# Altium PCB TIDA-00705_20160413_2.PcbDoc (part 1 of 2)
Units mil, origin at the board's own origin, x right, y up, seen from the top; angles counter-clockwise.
Board outline 1000 x 1000 mil, 6 copper layers (Top Layer, L2-GND-PLANE, L3-BUS, L4-BAT, L5-GND 1-PLANE, Bottom Layer), stack 0 mil thick; 66 components, 35 nets, 184 pads, 221 vias.
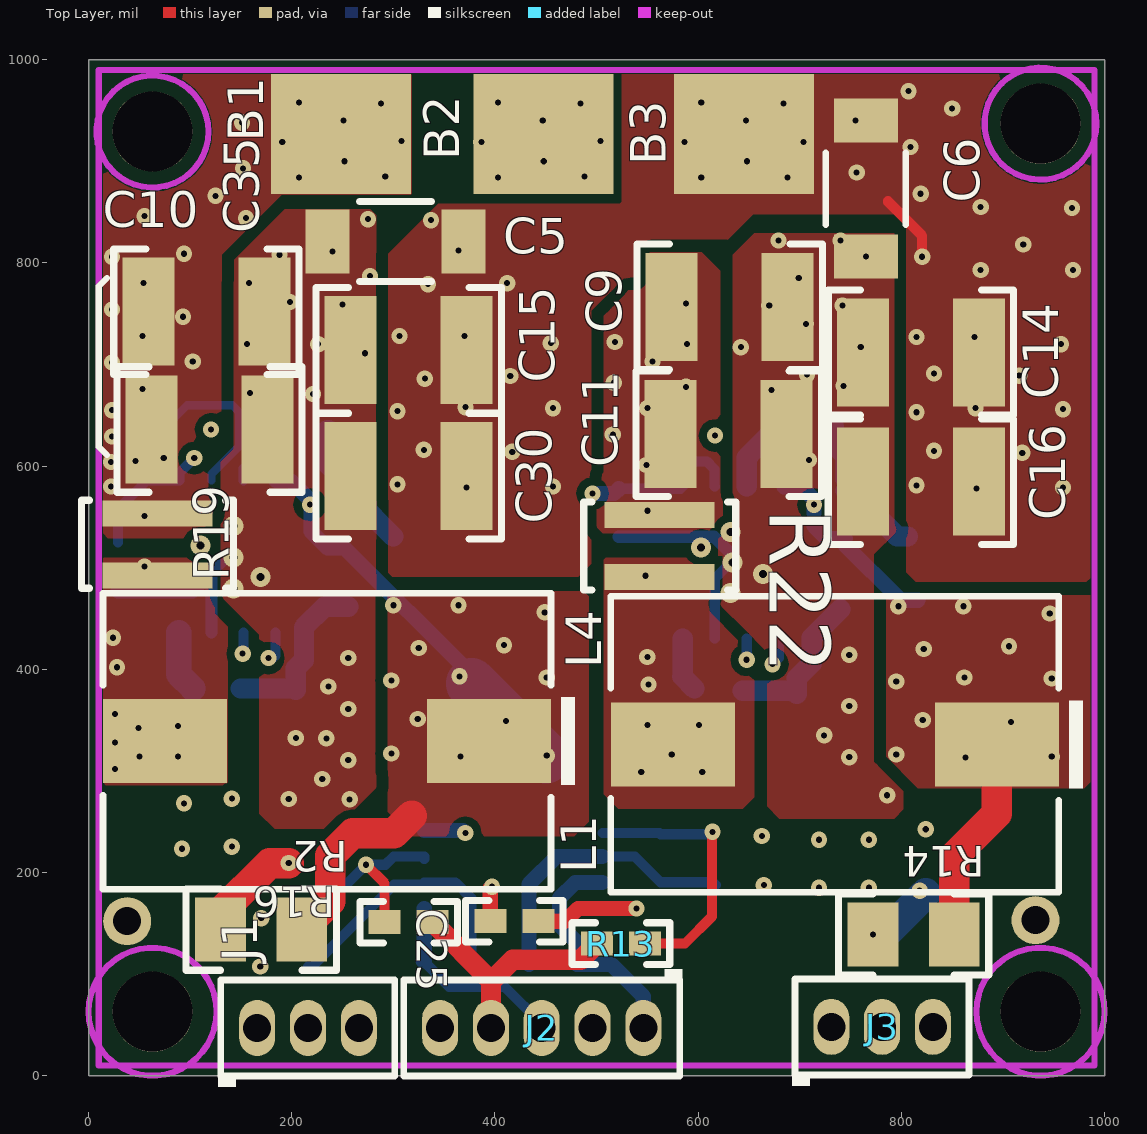
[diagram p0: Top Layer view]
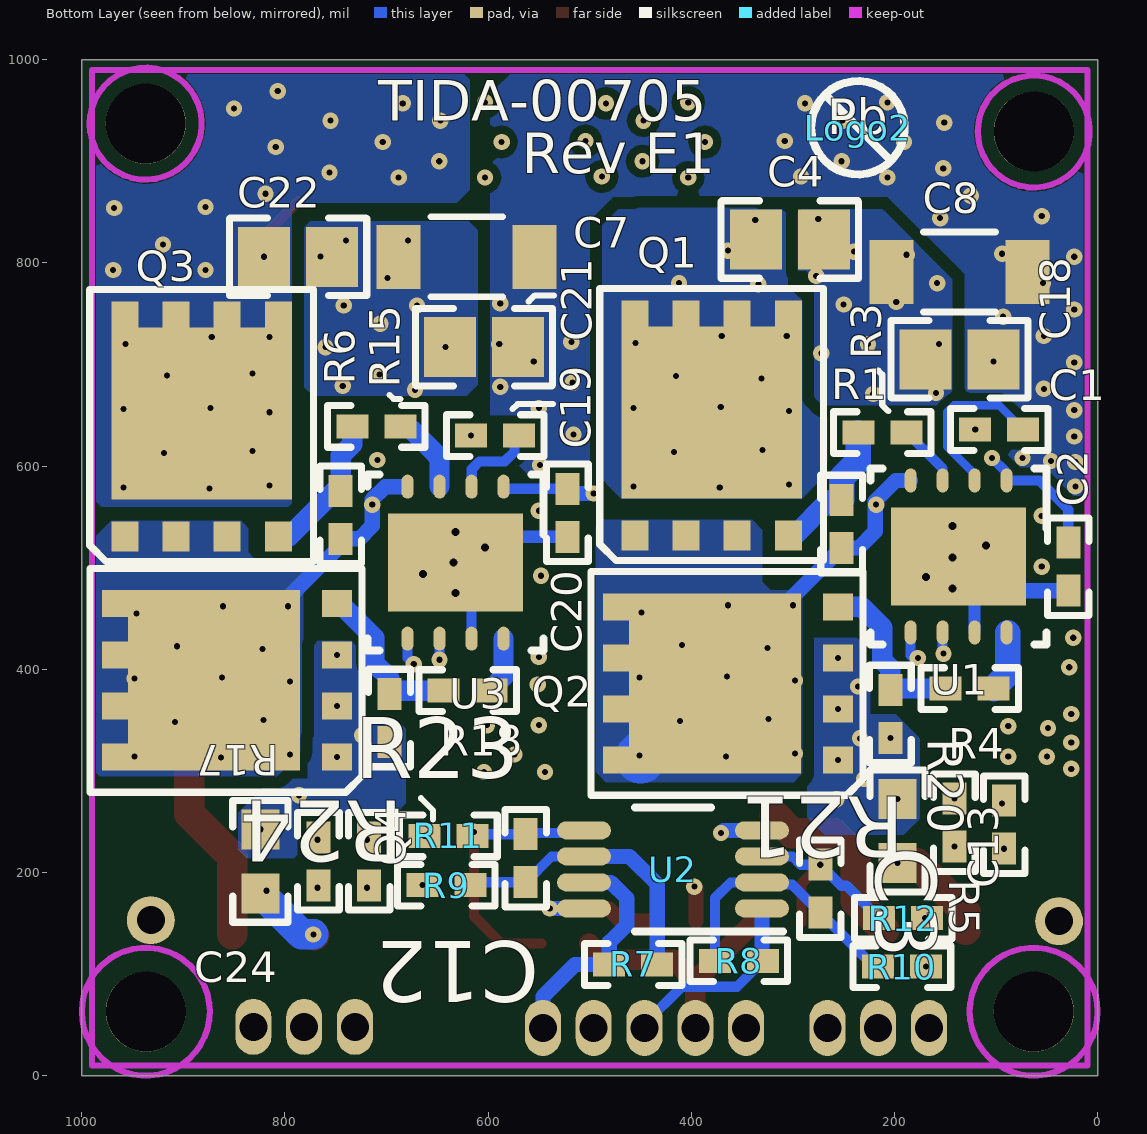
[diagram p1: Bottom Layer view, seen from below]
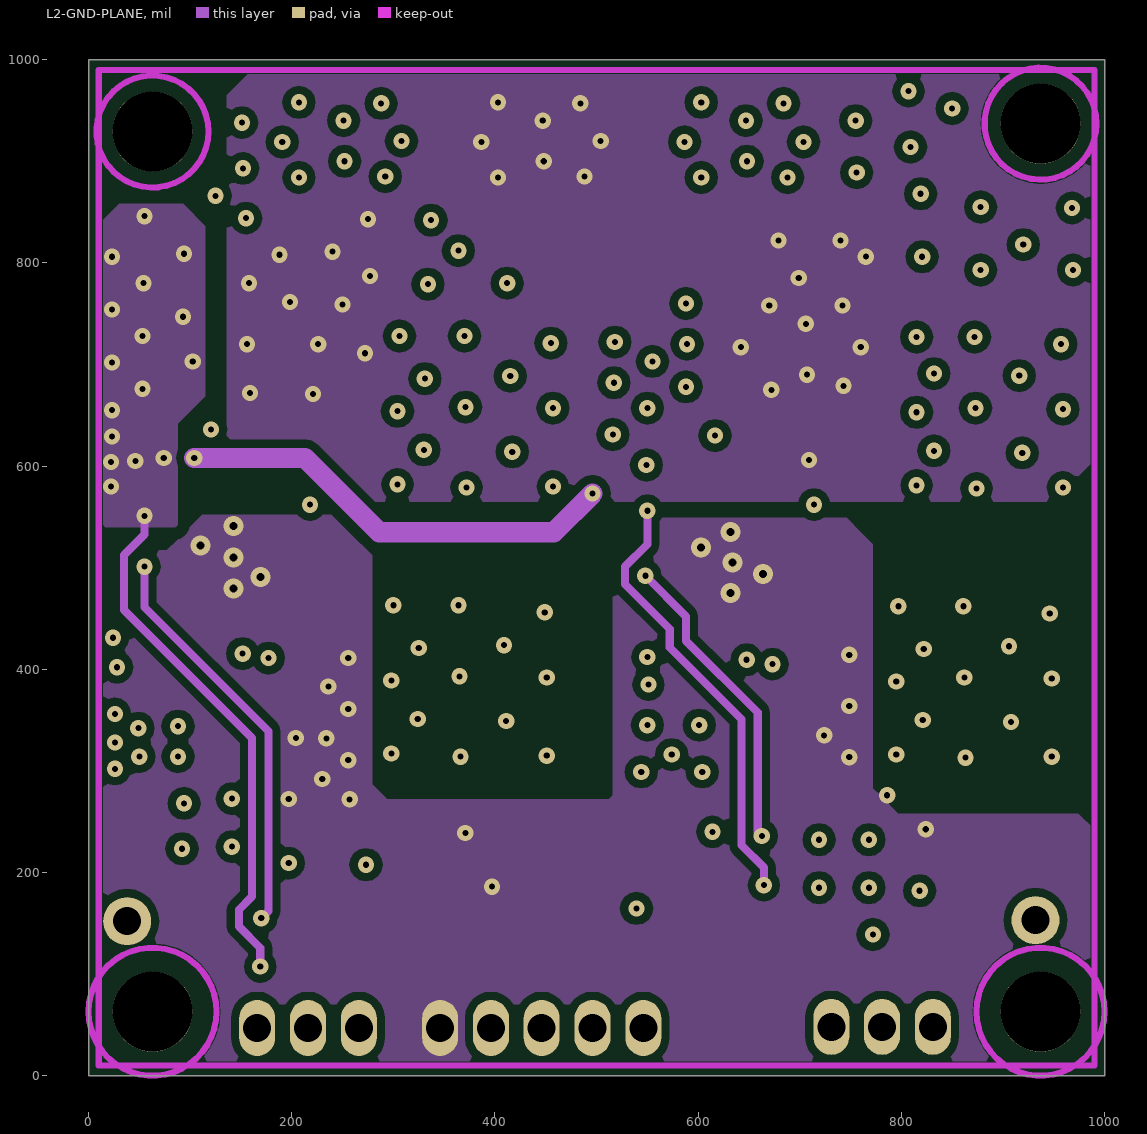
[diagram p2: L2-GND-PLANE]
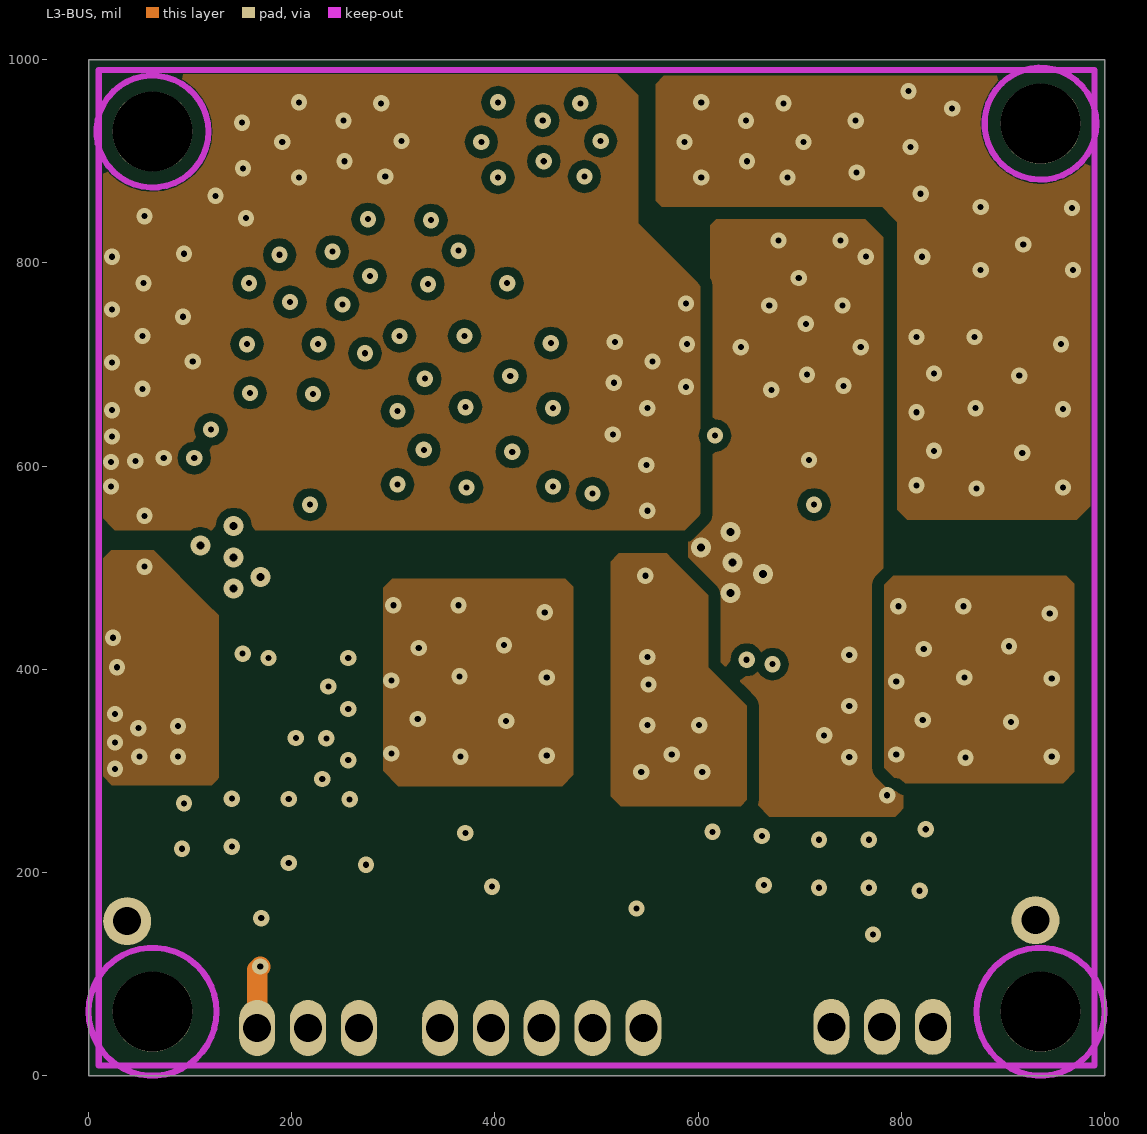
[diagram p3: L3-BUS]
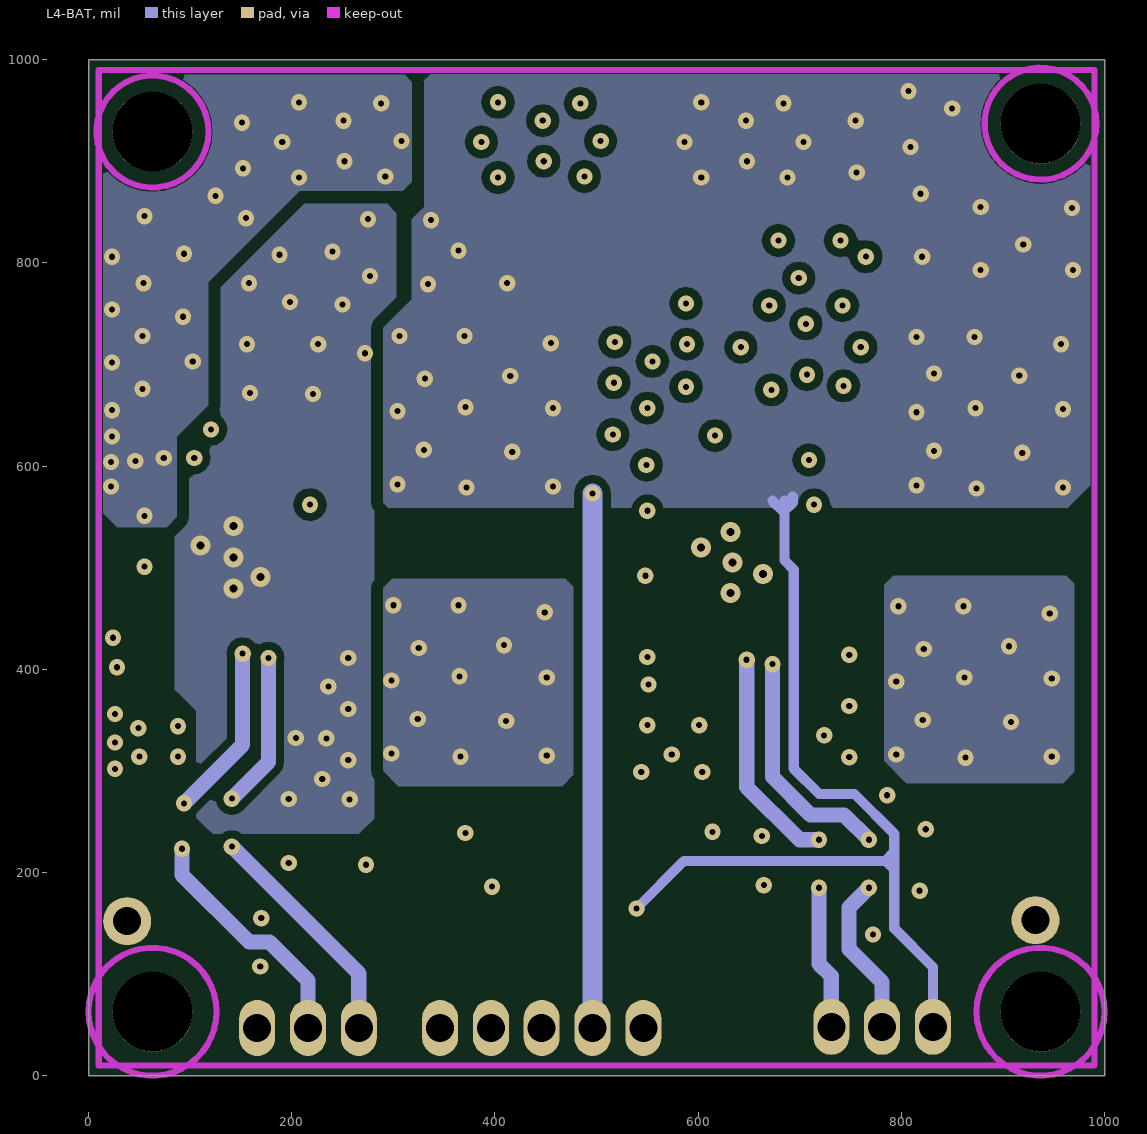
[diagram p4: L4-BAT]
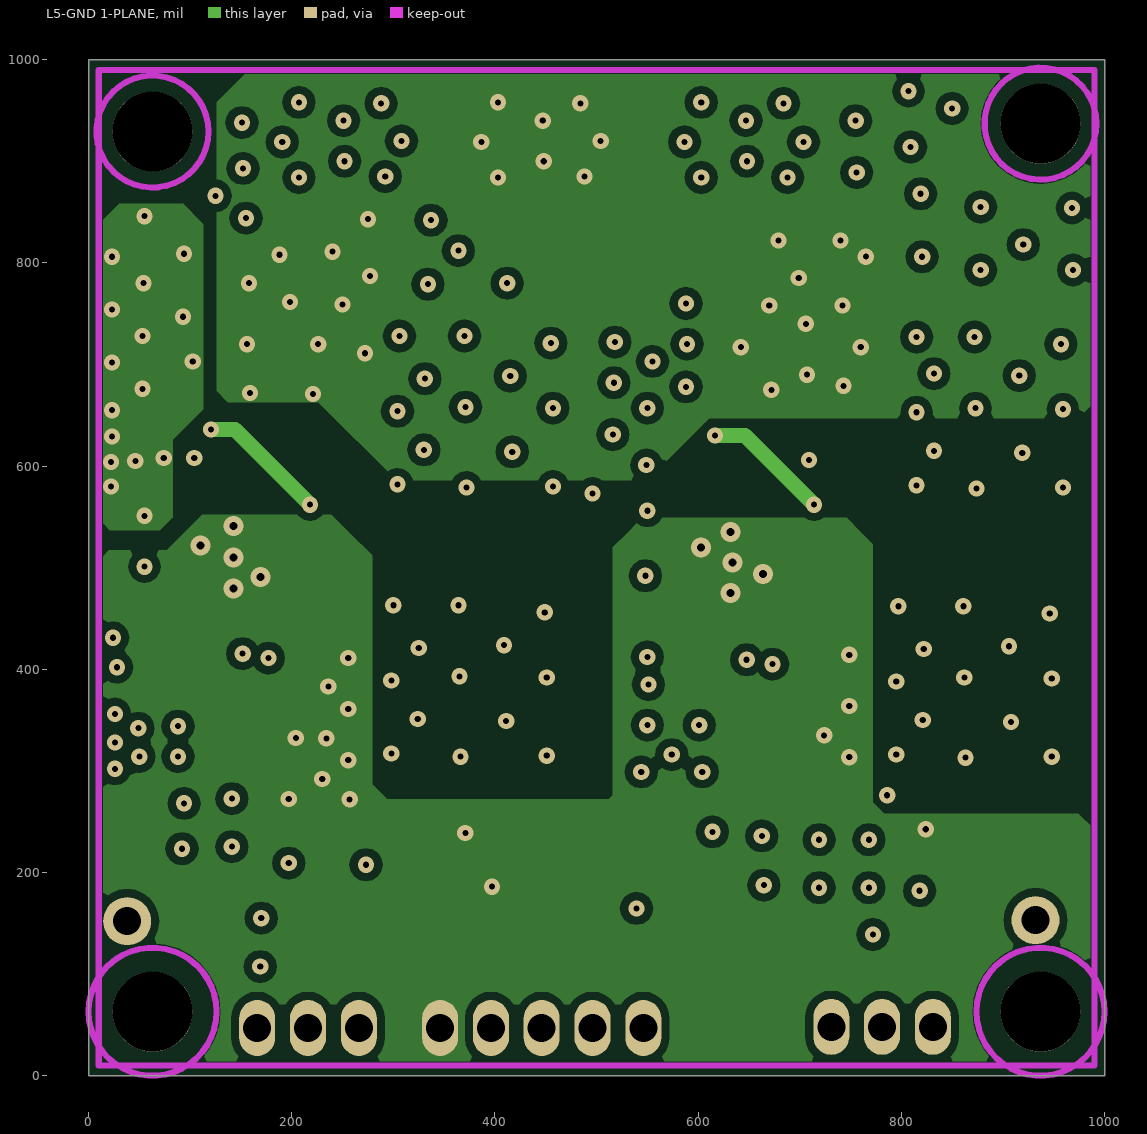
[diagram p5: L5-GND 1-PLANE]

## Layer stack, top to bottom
Top Layer: signal copper (thickness not stored)
L2-GND-PLANE: signal copper (thickness not stored)
L3-BUS: signal copper (thickness not stored)
L4-BAT: signal copper (thickness not stored)
L5-GND 1-PLANE: signal copper (thickness not stored)
Bottom Layer: signal copper (thickness not stored)

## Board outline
0,0 1000,0 1000,1000 0,1000

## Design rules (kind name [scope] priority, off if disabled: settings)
AcuteAngle [All] p1: minimum=4.50000000000000E+0001 checktracksonly=FALSE
AssemblyTestPointUsage [All] p1: valid=2
Clearance Keepout_via [IsKeepOut vs IsVia] p1: gap=1 except(6: Via-Via SMDPad-Via THPad-Via Track-Via)
Clearance Keepout_Polygon [IsKeepOut vs InPolygon] p2: gap=1
Clearance U2 [InComponent('U2') vs InComponent('U2')] p3: gap=7.5
Clearance "Clearance_Via to SMD" [IsVia vs IsSMTPin] p4: gap=0 except(6: SMDPad-Via Track-Via THPad-Via; 8: Via-Via)
Clearance keepout [IsKeepOut vs (InPadClass('All Pads'))] p5: gap=0.5
Clearance "Clearance_Poly to Poly" [InPolygon vs InPolygon] p6: gap=12
Clearance "Clearance_VIA TO VIA" [IsVia vs IsVia] p7: gap=8
Clearance Clearance_BoardEdge_MountingHoles [OnCopper and InComponentClass('Mounting Holes') vs IsKeepOut] p8: gap=40
Clearance [All] p9: gap=8
ComponentClearance ComponentClearance_1 [All] p1: gap=0 collisioncheckmode=3 verticalgap=0 showdistances=FALSE
DiffPairsRouting [All] p1: maxlimit=100 minlimit=10 mostfreqgap=10 toplayer_minwidth=15 toplayer_maxwidth=15 toplayer_prefwidth=15 midlayer1_minwidth=15 midlayer1_maxwidth=15 midlayer1_prefwidth=15 midlayer2_minwidth=15 midlayer2_maxwidth=15 midlayer2_prefwidth=15 midlayer3_minwidth=15 midlayer3_maxwidth=15 midlayer3_prefwidth=15 midlayer4_minwidth=15 midlayer4_maxwidth=15 midlayer4_prefwidth=15 bottomlayer_minwidth=15 bottomlayer_maxwidth=15 bottomlayer_prefwidth=15 maxuncoupledlength=1000
FabricationTestPointUsage TestPointUsage [All] p1: valid=2 allowmultiple=FALSE
FabricationTestpoint Testpoint [All] p1: side=3 testpointundercomponent=TRUE minsize=40 maxsize=100 preferedsize=60 minholesize=0 maxholesize=40 preferedholesize=32 testpointgrid=1 allowsidetop=TRUE allowsidebottom=TRUE usegrid=TRUE gridtolerance=0.01
FanoutControl Fanout_LCC [IsLCC] p1: bgadir=Out bgaviamode=Centered fanoutstyle=Auto fanoutdirection=Alternating viagrid=1 // Fanout_LCC (Default Rule)
FanoutControl Fanout_BGA [IsBGA] p2: bgadir=Out bgaviamode=Centered fanoutstyle=Auto fanoutdirection=Alternating viagrid=1 // Fanout_BGA (Default Rule)
FanoutControl Fanout_Default [All] p4: bgadir=Out bgaviamode=Centered fanoutstyle=Auto fanoutdirection=Alternating viagrid=1 // Fanout_Default (Default Rule)
FanoutControl Fanout_Small [(CompPinCount < 5)] p5: bgadir=Out bgaviamode=Centered fanoutstyle=Auto fanoutdirection=OutThenIn viagrid=1 // Fanout_Small (Default Rule)
HoleSize [All] p1: absolutevalues=TRUE maxlimit=251 minlimit=6 maxpercent=80.000 minpercent=20.000
MatchedLengths DiffPair_MatchedLengths_1 [All] p1: tolerance=1000 checknetsindiffpair=TRUE checkdiffpairvsdiffpair=TRUE checkothers=TRUE
MatchedLengths DiffPair_MatchedLengths_2 [InDifferentialPair ('NewDifferentialPair2')] p2: tolerance=1000 checknetsindiffpair=TRUE checkdiffpairvsdiffpair=TRUE checkothers=TRUE
MatchedLengths il1MatchedLengths [InDifferentialPair ('NewDifferentialPair1')] p3: tolerance=1000 checknetsindiffpair=TRUE checkdiffpairvsdiffpair=TRUE checkothers=TRUE
MatchedLengths DiffPair_MatchedLengths_3 [InDifferentialPair ('NewDifferentialPair1')] p4: tolerance=1000 checknetsindiffpair=TRUE checkdiffpairvsdiffpair=TRUE checkothers=TRUE
MatchedLengths DiffPair_MatchedLengths_4 [InDifferentialPair ('OP AMP')] p5: tolerance=1000 checknetsindiffpair=TRUE checkdiffpairvsdiffpair=TRUE checkothers=TRUE
MatchedLengths DiffPair_MatchedLengths_1_1 [InDifferentialPair ('OP AMP')] p6: tolerance=1000 checknetsindiffpair=TRUE checkdiffpairvsdiffpair=TRUE checkothers=TRUE
MinimumAnnularRing MinimumAnnularRing_1 [(InComponent('J1') AND InComponent('J2') AND InComponent('J3'))] p1: minimumring=3
MinimumAnnularRing MinimumAnnularRing_ThermalPadVias [IsVia and InAnyComponent] p2: minimumring=3
MinimumAnnularRing [All] p3: minimumring=3
MinimumSolderMaskSliver MinimumSolderMaskSliver_Logo [InComponentClass('Logo') vs InComponentClass('Logo')] p1: minsoldermaskwidth=0.7
MinimumSolderMaskSliver [All] p2: minsoldermaskwidth=3.94
PlaneClearance [All] p1: clearance=16
PlaneConnect [All] p1: planeconnectstyle=Direct reliefexpansion=10 reliefentries=4 reliefconductorwidth=10 reliefairgap=10
PolygonConnect [All] p1: connectstyle=Direct reliefconductorwidth=10 reliefentries=4 polygonreliefangle="90 Angle" airgapwidth=10
RoutingVias ThermalPadVias [IsVia and InAnyComponent] p1: holewidth=7.87 width=19.68 viastyle="Through Hole" minholewidth=7.87 minwidth=19.68 maxholewidth=12.99 maxwidth=23.62
RoutingVias RoutingVias_PWR [All] p2: holewidth=6 width=16 viastyle="Through Hole" minholewidth=6 minwidth=16 maxholewidth=7.78 maxwidth=19.68
RoutingVias [All] p3: holewidth=6 width=16 viastyle="Through Hole" minholewidth=6 minwidth=16 maxholewidth=6 maxwidth=16
SMDToCorner [All] p1: distance=30000
SilkToBoardRegionClearance [All] p1 off:
SilkToSilkClearance [All] p1 off: silktosilkclearance=5
SilkToSolderMaskClearance SilkscreenOverComponentPads [IsPad] p1 off: minsilkscreentomaskgap=5 clearancetoexposedcopper=TRUE
SolderMaskExpansion [All] p1: expansion=2.5
UnpouredPolygon [All] p1: allowunpoured=FALSE
ViasUnderSMD [All] p1: allowed=TRUE
Width Width_PWR [InNetClass('PWR')] p1: maxlimit=100 minlimit=8 preferedwidth=8
Width [All] p2: maxlimit=100 minlimit=6 preferedwidth=8 checkconnectedcopper=TRUE
13 further rules are at their usual default settings.

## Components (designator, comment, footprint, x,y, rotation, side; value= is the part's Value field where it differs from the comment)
B1 "SMD" B1#1 1507.87,123 r180 top
B2 "SMD" B1#2 1314.87,123 r180 top
B3 "SMD" B1#3 1121.87,123 r180 top
C1 "06033C104JAT2A" 0402 96.87,636 r0 bottom
C2 "GRM188R61E105KA12D" 0402 28.87,501 r270 bottom
C3 "885012205031" 0402 273,184 r90 bottom
C4 "12103C106KAT2A" 0805 303,823 r180 bottom
C5 "12103C106KAT2A" 1206_190 302,821 r180 top
C6 "12103C106KAT2A" 1206_190 765,873 r270 top
C7 "12103C106KAT2A" 1206_190 621,806 r0 bottom
C8 "12103C106KAT2A" 1206_190 136,791 r0 bottom
C9 "12103C106KAT2A" 1210 631,756.72 r0 top
C10 "12103C106KAT2A" 1210 119,636 r0 top
C11 "12103C106KAT2A" 1210 630,631.72 r0 top
C12 "885012205031" 0402 563,214 r90 bottom
C13 "06031C222KAT2A" 0603 197,240.69 r90 bottom
C14 "12103C106KAT2A" 1210 819.24,711.69 r180 top
C15 "12103C106KAT2A" 1210 315.04,714 r180 top
C16 "12103C106KAT2A" 1210 819.24,584.69 r180 top
C18 "12103C106KAT2A" 0805 136,705 r0 bottom (schematic designator C8)
C19 "06033C104JAT2A" 0402 593,630 r0 bottom
C20 "GRM188R61E105KA12D" 0402 521.87,554 r270 bottom
C21 "12103C106KAT2A" 0805 604,717 r0 bottom
C22 "12103C106KAT2A" 0805 787,806 r180 bottom
C24 "06031C222KAT2A" 0603 824,211 r90 bottom
C25 "C0603C104Z4VACTU" 0402 419,152 r180 top
C30 "12103C106KAT2A" 1210 315.04,590 r180 top
C35 "12103C106KAT2A" 1210 116,752 r0 top
J1 "GRPB031VWVN-RC" Sullins_GRPB031VWVN-RC 216,47 r0 top locked
J2 "GRPB051VWVN-RC" Sullins_GRPB051VWVN-RC 446,47 r180 top locked
J3 "GRPB031VWVN-RC" Sullins_GRPB031VWVN-RC 781,48 r0 top locked
L1 "FP1107R1-R23-R" FP1107R1 234.6,329.15 r180 top
L4 "FP1107R1-R23-R" FP1107R1 734.47,326.15 r180 top
Logo1 "Texas Instruments" TI_Symbol_Overlay_Small 587,-159 r180 bottom
Logo2 "Pb-Free Symbol" Pb-Free_Overlay_Small 236,933 r180 bottom
Q1 "CSD16325Q5C" TRANS_NexFET_Q5C 380,641 r90 bottom locked
Q2 "CSD16325Q5C" TRANS_NexFET_Q5C 364.87,386 r0 bottom locked
Q3 "CSD16325Q5C" TRANS_NexFET_Q5C 882,640 r90 bottom
Q4 "CSD16325Q5C" TRANS_NexFET_Q5C 858,389 r0 bottom
R1 "CRCW04021K05FKED" 0402 252,543 r90 bottom
R2 "RR1220Q-100-D" 0805_HV 169.88,143.72 r0 top
R3 "CRCW04020000Z0ED" 0402 212,633 r0 bottom
R4 "CRCW04020000Z0ED" 0402 126,381 r0 bottom
R5 "CRCW04021K05FKED" 0402 141,249 r270 bottom
R6 "CRCW04021K05FKED" 0402 745,552 r90 bottom
R7 "CRCW04021K05FKED" 0402 457.13,109.42 r0 bottom
R8 "CRCW04021K05FKED" 0402 353.13,113 r180 bottom
R9 "CRCW04021K05FKED" 0402 641,187.5 r180 bottom
R10 "CRCW04021K05FKED" 0402 192.62,107.35 r0 bottom
R11 "CRCW04021K05FKED" 0402 639,236 r180 bottom
R12 "CRCW04021K05FKED" 0402 191.5,155 r0 bottom
R13 "CRCW04021K05FKED" 0402 524,130 r0 top
R14 "RR1220Q-100-D" 0805_HV 812,139 r0 top
R15 "CRCW04020000Z0ED" 0402 710,639 r0 bottom
R16 "CRCW04021K05FKED" 0402 315,151 r180 top
R17 "CRCW04021K05FKED" 0402 767,211 r270 bottom
R18 "CRCW04020000Z0ED" 0402 620,379 r0 bottom
R19 "PRL1632-R005-F-T1" 0612 68,523 r90 top
R20 "CRCW04021K05FKED" 0402 92,247 r270 bottom
R21 "CRCW04021K05FKED" 0402 204,356 r90 bottom
R22 "PRL1632-R005-F-T1" 0612 562.13,521.28 r90 top
R23 "CRCW04021K05FKED" 0402 717,211 r270 bottom
R24 "CRCW04021K05FKED" 0402 697,352 r90 bottom
U1 "UCC27211D" DRM0008A 136.87,511 r270 bottom
U2 "OPA2192IDGKR" DGK0008A_N 418,203 r0 bottom
U3 "UCC27211D" DRM0008A 632,505 r270 bottom

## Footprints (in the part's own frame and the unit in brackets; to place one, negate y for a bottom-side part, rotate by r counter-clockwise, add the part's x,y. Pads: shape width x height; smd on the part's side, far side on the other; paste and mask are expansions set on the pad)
0402 [mm] "0402 from SM-752 data"
  rect 0.8x0.6 smd: 1(-0.6,0) 2(0.6,0)
  silkscreen extent -1.22,-0.52 1.22,0.52, body extent -0.55,-0.3 0.55,0.3, height 0.6
0603 [mm] "0603 from SM-752 data"
  rect 1x0.95 smd: 1(-0.8,0) 2(0.8,0)
  silkscreen extent -1.52,-0.69 1.52,0.69, body extent -0.87,-0.47 0.87,0.47, height 1
0612 [mm] "Panasonic recommended land pattern, fb97d03ed01.pdf dated April 2008"
  rect 0.65x2.75 smd: 1(-0.775,0) 2(0.775,0)
  silkscreen extent -1.1,-1.9 1.1,1.9, body extent -0.9,-1.7 0.9,1.7, height 0.85
0805 [mm] "0805 from SM-752 data"
  rect 1.3x1.5 smd: 1(-0.85,0) 2(0.85,0)
  silkscreen extent -1.72,-0.97 1.72,0.97, body extent -1.1,-0.72 1.1,0.72, height 1.45
0805_HV [mil] "0805 with 30mil clearance between pads"
  rect 50x63 smd: 1(-40,0) 2(40,0)
  silkscreen extent -74,-40 74,40, body extent -43,-29 43,29, height 57
1206_190 [mm] "1206_190"
  rect 1.1x1.6 smd: 1(-1.7,0) 2(1.7,0)
  silkscreen extent -0.9,-1 0.9,1, body extent -1.75,-0.95 1.75,0.95, height 1.9
1210 [mm] "1210 from SM-752 data"
  rect 1.3x2.7 smd: 1(-1.45,0) 2(1.45,0)
  silkscreen extent -2.32,-1.57 2.32,1.57, body extent -1.7,-1.35 1.7,1.35, height 1.35
B1#1 [mm]
  rect 3.5x3 smd: 1(31.991,-20.422)
B1#2 [mm]
  rect 3.5x3 smd: 1(22.027,-20.422)
B1#3 [mm]
  rect 3.5x3 smd: 1(12.113,-20.422)
DGK0008A_N [mm] "TSOP, 8-Leads, Body 3x3mm, Pitch 0.65mm, IPC Medium Density"
  oval 1.35x0.45 smd: 1(-2.225,0.975) 2(-2.225,0.325) 3(-2.225,-0.325) 4(-2.225,-0.975) 5(2.225,-0.975) 6(2.225,-0.325) 7(2.225,0.325) 8(2.225,0.975)
  silkscreen extent -2.75,-1.55 0.95,1.55, body extent -2.45,-1.5 2.45,1.5, height 0.96
DRM0008A [mm] "TI"
  oval 0.6x0.3 smd: 1(-1.9,1.2) 2(-1.9,0.4) 3(-1.9,-0.4) 4(-1.9,-1.2) 5(1.9,-1.2) 6(1.9,-0.4) 7(1.9,0.4) 8(1.9,1.2)
  rect 2.45x3.38 smd paste-1.25: 9(0,0)
  silkscreen extent -2.2,-2.2 2.2,2.2, body extent -2.05,-2.05 2.05,2.05, height 1.01
FP1107R1 [mm] "COILTRONICS"
  rect 3.1x2.1 smd: 1(-4.05,0) 2(4.05,0)
  silkscreen extent -6.2,-3.7 5.6,3.7, body extent -5.5,-3.6 5.5,3.6, height 7.51
Pb-Free_Overlay_Small [mil]
  silkscreen extent -46,-46 46,46
Sullins_GRPB031VWVN-RC [mm] "SULLINS"
  oval 0.9x1.4 hole 0.7: 1(-1.27,0) 2(0,0) 3(1.27,0)
  silkscreen extent -2.25,-1.47 2.17,1.2, body extent -2.15,-1.17 2.17,1.17, height 4.2
Sullins_GRPB051VWVN-RC [mm] "SULLINS"
  oval 0.9x1.4 hole 0.7: 1(-2.54,0) 2(-1.27,0) 3(0,0) 4(1.27,0) 5(2.54,0)
  silkscreen extent -3.52,-1.47 3.45,1.2, body extent -3.42,-1.17 3.42,1.17, height 4.2
TI_Symbol_Overlay_Small [mil]
  silkscreen extent -90,-88 91,88
TRANS_NexFET_Q5C [mm] "TI recommended land pattern (nominal) M0139-01"
  rect 0.75x0.675 smd mask+0.051: 1(-2.776,1.917) 2(-2.776,0.639) 3(-2.776,-0.639) 4(-2.776,-1.917)
  rect 0.655x0.675 smd mask+0.051: 5(2.776,-1.917) 6(2.776,-0.639) 7(2.776,0.639) 8(2.776,1.917)
  rect 4.295x4.51 smd paste-2.2 mask+0.051: 10(0.301,0)
  silkscreen extent -3.4,-2.8 3.4,2.8, body extent -3.05,-2.55 3.05,2.55, height 1.06

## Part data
B1 B2 B3: library part TP_30X40MIL, "Test Point, SM, 2x3mm"
C1 C19: "CAP, CERM, 0.1 µF, 25 V, +/- 5%, X7R, 0603"
C2 C20: "CAP, CERM, 1 µF, 25 V, +/- 10%, X5R, 0603"
C3 C12: "CAP, CERM, 0.01 µF, 16 V, +/- 10%, X7R, 0402"
C4 C5 C6 C7 C8 C9 C10 C11 C14 C15 C16 C18 C21 C22 C30 C35: "CAP, CERM, 10 µF, 25 V, +/- 10%, X7R, 1210"
C13 C24: "CAP, CERM, 2200 pF, 100 V, +/- 10%, X7R, 0603"
C25: "CAP, CERM, 0.1 µF, 16 V, +80/-20%, Y5V, 0603"
J1 J3: "Header, 50mil, 3x1, Gold, TH"
J2: "Header, 50mil, 5x1, Gold, TH"
L1 L4: "Inductor, Wirewound, Ferrite, 230nH, 45A, 0.00029 ohm, SMD"
Logo1: library part TI_Logo, "Texas Instrument Corporate Signature"
Logo2: library part Pb-Free
Q1 Q2 Q3 Q4: "MOSFET, N-CH, 25 V, 100 A, DualCool SON 5x6mm"
R1 R5 R6 R7 R8 R9 R10 R11 R12 R13 R16 R17 R20 R21 R23 R24: "RES, 1.05 k, 1%, 0.063 W, 0402"
R2 R14: "RES, 10.0, 0.5%, 0.1 W, 0805"
R3 R4 R15 R18: "RES, 0, 5%, 0.063 W, 0402"
R19 R22: "RES, 0.0005, 1%, 1 W, 0612"
U1 U3: "120-V Boot, 4-A Peak, High Frequency High-Side and Low-Side Driver, D0008A"
U2: "36-V, Precision, Rail-to-Rail Input/Output, Low Offset Voltage, Low Input Bias Current Op Amp with e-trim, DGK0008A"

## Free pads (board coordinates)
  round 47.24 hole 27.56: 0(38,152) 0(932,153)
  round 78.74 hole 78.74 unplated mask+10: 0(62.87,929.25) 0(62.99,62.99) 0(936.87,62.99) 0(937.01,937.01)

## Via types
v1: diameter 16, hole 6, Top Layer to Bottom Layer, 211 vias
v2: diameter 19.68, hole 7.87, Top Layer to Bottom Layer, 10 vias

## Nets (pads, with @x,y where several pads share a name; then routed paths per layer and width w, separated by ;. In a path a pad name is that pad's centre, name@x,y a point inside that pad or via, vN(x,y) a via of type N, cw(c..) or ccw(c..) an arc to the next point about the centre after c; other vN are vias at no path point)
8.2V: C2.1 C20.1 J2.2 U1.1 U3.1 | length 1188.9
  L2-GND-PLANE w20: v1(104,608) 213,608 286,535 458,535 v1(496,573)
  L4-BAT w20: J2.2@496,47 v1(496,573)
  Bottom Layer w10: C2.1@28.87,524.62 28.87,557.18 57.5,585.8 U1.1@89.63,585.8 89.63,593.63 v1(104,608) ; C20.1@521.87,577.62 582.57,577.62 U3.1@584.76,579.8
  Bottom Layer w15: v1(496,573) 517.25,573 C20.1@521.87,577.62
BAT+: B3.1 C4.1 C5.1 C6.1 C14.1 C15.1 C16.1 C22.1 C25.1 C30.1 J3.3 Q1.5 Q1.6 Q1.7 Q1.8 Q1.10 Q3.5 Q3.6 Q3.7 Q3.8 Q3.10 U2.8 | length 1125.8
  Top Layer w10: 787,861 787,860 820.46,826.54 v1(820.46,806)
  Top Layer w15: C25.1@442.62,152 469,152 481.61,164.61 v1(539.28,164.61)
  L4-BAT w10: v1(539.28,164.61) 585.91,211.24 784,211.24 ; 673,566 684,555 ; 685,566 685,556 ; 693.04,570 693.04,564.04 685,556 ; J3.3@831,59 831,107 793,145 793,203 ; 684,555 685,555 ; 684,555 685,556 ; 685,555 685,556 ; 685,555 685,507.15 694.13,498.02 694.13,302.18 719.15,277.15 753.85,277.15 793,238 793,220.24 ; 784,211.24 784.76,211.24 ; 784,211.24 793,220.24 ; 784.76,211.24 793,211.24 ; 784.76,211.24 793,203 ; 793,203 793,211.24 ; 793,211.24 793,220.24
  L4-BAT w15: v1(539.28,164.61) v1@539.9,164
  Bottom Layer w15: U2.8@505.6,164.61 v1(539.28,164.61)
  other v1: 874,578 372,579 959,579 457,580 815,581 304,582 919,613 417,614 832,615 330,616 815,653 304,654 959,656 457,657 873,657 371,658 331,686 415,688.69 916,689 832,691 957,720 455,721 815,727 872,727 306,728 370,728 334,779 412,780 878,793 969,793 364,812 920,818 337,842 968,854 878,855 819,868 603,884 688,884 756,889 648,900 809,914 586.61,919 703.61,919 647,940 755,939.93 850,952 684,957 603,958 807,969
BUS+: B1.1 C7.1 C8.1 C9.1 C10.1 C11.1 C18.1 C21.1 C35.1 J1.1 R9.1 R10.1 R19.2 R22.2 | length 1022.6
  Top Layer w20: J1.1@165,41 J1.1@171,35
  L2-GND-PLANE w8: v1(55,551) 55,532.63 35,512.63 35,458.37 161,332.37 161,176.41 147.88,163.28 147.88,146.72 169,125.59 v1(169,107.35) ; v1(550,556) 550,523 528,501 528,483.72 572,439.72 572,421.37 642.62,350.75 642.62,226.8 664.62,204.8 v1(664.62,187.5)
  L3-BUS w20: J1.1@166,47 166,104.35 v1(169,107.35)
  other v1: 22,580 549,601 22,604 46,605 74,608 23,629 516,631 23,655 550,657 53,676 588,678 517,682 23,702 102.54,703 555,703 589,720 518,722 53,728 93,747 23,754 588,760 54,780 23,806 94,809 155,844 55,846 125,866 207,884 292,885 152,893 252,900 190.61,919 308,920 151,938 251,940 288,957 207,958
GND: B2.1 C2.2 C4.2 C5.2 C6.2 C7.2 C8.2 C9.2 C10.2 C11.2 C13.2 C14.2 C15.2 C16.2 C18.2 C20.2 C21.2 C22.2 C24.2 C25.2 C30.2 C35.2 J2.5 Q2.1 Q2.2 Q2.3 Q4.1 Q4.2 Q4.3 R21.1 R24.1 U1.7 U1.9 U2.4 U3.7 U3.9 | length 456.8
  Top Layer w15: C25.2@395.38,152 395.38,184.38 v1(397,186)
  Bottom Layer w10: U3.7@616.25,430.2 616.25,489.25 U3.9@632,505 v2(634,505)
  Bottom Layer w12: U1.7@121.13,436.2 121.13,494.25 120.13,495.25 U1.9@135.87,511 ; C20.2@521.87,530.38 615.62,530.38 U3.9@632,514
  Bottom Layer w15: C2.2@28.87,477.38 102.25,477.38 U1.9@120.13,495.25 ; U2.4@330.4,241.39 368.22,241.39 v1(370.8,238.8)
  other v1: 824,242.5 197,272.19 257,272 786,276 230,292 255.57,310.51 748.7,313.51 204,332.38 234,332 724,335 255.57,360.84 748.7,363.84 236,383 255.57,411.16 748.7,414.16 709,606 221,671 159,672 672,675 743,679 707,690 272,711 642,717 760,717 156,720 226,720 706,740 670,758 742,758 250,759 198.25,761.46 158,780 699,785 277,787 765,806.07 188,808 240,811 679,822 740,822 275,843 403,884 488,885 448,900 386.61,919 504,920 447,940 484,957 403,958
  other v2: 632,475 142.8,479.69 169,491 664,494 142.8,510 603,520 110,522 632,535 142.8,541
H1_PWM: J1.3 R5.2 | length 230.2
  L4-BAT w15: v1(141,225.38) 266,100.38 J1.3@266,47
H2_PWM: J3.2 R17.2 | length 158.5
  L4-BAT w15: v1(768,185) 748.5,165.5 748.5,124.5 781,92 J3.2@781,48
IL1: J2.3 R8.2 U2.1 | length 198.1
  Bottom Layer w10: R8.2@329.51,113 354.95,87.56 409.43,87.56 446,50.99 J2.3@446,47
  Bottom Layer w15: R8.2@329.51,113 330.4,113.89 U2.1@330.4,164.61
IL1+: L1.2 R12.1 R19.1 | length 399.4
  L2-GND-PLANE w8: v1(55,501) 55,461 177,339 177,162 v1(170,155)
  other v1: 26,302 50,314 88,314 26,328 49,342 88,344 26,356 28,402 24,431
IL2: J2.1 R7.2 U2.7 | length 230.2
  Bottom Layer w15: U2.7@505.6,190.2 479.03,190.2 463.52,174.7 463.52,148.48 480.76,131.24 R7.2@480.76,109.42 514.58,109.42 546,78 J2.1@546,47
IL2+: L4.2 R11.1 R22.1 | length 303.5
  L2-GND-PLANE w8: v1(548,492) 588,452 588,428 658.62,357.38 658.62,240 v1(662.62,236)
  other v1: 544,299 604,299 574,316 550,345 601,345 551,385 550,412
L1_PWM: J1.2 R20.2 | length 248.6
  L5-GND 1-PLANE w15: J1.2@219,48 J1.2@225.5,54.5
  L4-BAT w15: v1(92,223.38) 92,197.64 158.14,131.5 178.08,131.5 216,93.58 J1.2@216,47
L2_PWM: J3.1 R23.2 | length 142
  L4-BAT w15: v1(719,185) 719,110 731,98 J3.1@731,48
NetC1_1: C1.1 U1.2 | length 166.2
  Bottom Layer w8: C1.1@73.25,636 97.06,659.81 141.56,659.81 148.24,653.13 148.24,619.22 121.13,592.1 U1.2@121.13,585.8
NetC1_2: C1.2 L1.1 Q1.1 Q1.2 Q1.3 Q2.5 Q2.6 Q2.7 Q2.8 Q2.10 R1.1 R2.2 U1.4 | length 710.5
  Top Layer w30: R2.2@209.88,143.72 237.88,171.72 237.88,216.34 260.16,238.62 300.62,238.62 318,256
  L5-GND 1-PLANE w15: v1(120.5,636) 144,636 v1(218,562)
  Bottom Layer w15: U1.4@184.12,585.8 198.76,585.8 218.91,565.65 218.91,562.09 219,562 219,535.5 235.12,519.38 R1.1@252,519.38 376.74,394.64 Q2.10@376.74,386
  Bottom Layer w50: Q2.10@376.74,386 Q2.10@449.96,312.78
  other v1: 366,314 451,315 298,317 411,349 324,351 298,389 451,392 365,393 325,421 409,423.69 449,456 300,463 364,463
NetC3_1: C3.1 R8.1 R10.2 U2.2 | length 266.6
  Bottom Layer w10: R10.2@216.24,107.35 219.97,107.35 C3.1@273,160.38 300.65,188.03 328.23,188.03 U2.2@330.4,190.2 361.3,190.2 376.76,174.74 R8.1@376.76,113 R8.1@376.76,109.42
NetC3_2: C3.2 R12.2 R16.2 U2.3 | length 204.8
  Top Layer w10: v1(273,207.62) 291.38,189.24 R16.2@291.38,151
  Bottom Layer w10: R12.2@215.12,155 247.12,187 252.38,187 v1(273,207.62) 292.12,207.62 300.3,215.8 U2.3@330.4,215.8 ; U2.3@330.4,213.21 U2.3@330.54,213.21
NetC12_1: C12.1 R7.1 R9.2 U2.6 | length 286
  Bottom Layer w10: U2.6@505.6,215.8 537.58,215.8 C12.1@563,190.38 614.5,190.38 R9.2@617.38,187.5
  Bottom Layer w15: R7.1@433.51,109.42 433.51,188.51 460.8,215.8 U2.6@505.6,215.8
NetC12_2: C12.2 R11.2 R13.2 U2.5 | length 269.1
  Top Layer w10: R13.2@547.62,130 587,130 613.76,156.76 613.76,239.76 v1(614,240)
  Bottom Layer w10: U2.5@505.73,238.8 561.82,238.8 C12.2@563,237.62 R11.2@613.76,237.62
NetC13_1: C13.1 R2.1 | length 104.3
  Top Layer w30: R2.1@129.88,143.72 129.88,160.84 178.23,209.2 v1(197,209.2)
NetC19_1: C19.1 U3.2 | length 83.1
  Bottom Layer w10: C19.1@569.38,629 574,624.38 574,614.19 583.57,604.61 608.39,604.61 616,597 616,580.06 U3.2@616.25,579.8
NetC19_2: C19.2 L4.1 Q3.1 Q3.2 Q3.3 Q4.5 Q4.6 Q4.7 Q4.8 Q4.10 R6.1 R14.2 U3.4 | length 522.2
  Top Layer w30: R14.2@852,139 852,216 893.92,257.92 L4.1@893.92,326.15
  L5-GND 1-PLANE w15: v1(616.62,630) 646.04,630 v1(714.04,562)
  Bottom Layer w15: U3.4@684.45,579.55 701.44,579.55 714.04,566.96 v1(714.04,562) 714.04,541 726.66,528.38 R6.1@745,528.38 ; R6.1@744,523 799,468 Q4.10@816.38,468
  other v1: 863,313 948,314 795,316 908,348 821,350 795,388 948,391 862,392 822,420 906,422.69 946,455 797,462 861,462
NetC24_1: C24.1 R14.1 | length 70.2
  Top Layer w30: R14.1@771,138 v1(772,139)
  Bottom Layer w30: v1(772,139) 783.5,139 822.25,177.75 C24.1@824,179.5
  other v1: 818,182
NetQ1_4: Q1.4 R1.2 R3.2 | length 135.9
  Bottom Layer w20: R1.2@252,566.62 263.77,566.62 Q1.4@299.8,530.6
  Bottom Layer w25: R3.2@235.62,633 235.62,604.87 252,588.5 R1.2@252,566.62
NetQ2_4: Q2.4 R4.2 R21.2 | length 171.8
  Bottom Layer w20: R4.2@149.62,381 202.62,381 R21.2@204,379.62 204,401 212,409 212,441.13 232.37,461.49 Q2.4@255.57,461.49
NetQ3_4: Q3.4 R6.2 R15.2 | length 137.2
  Bottom Layer w20: R15.2@733.62,639 733.62,621.38 745,610 R6.2@745,586.62 ; R6.2@745,575.62 750.77,575.62 795.7,530.7 Q3.4@806.51,530.7
NetQ4_4: Q4.4 R18.2 R24.2 | length 155.9
  Bottom Layer w20: R18.2@643.62,379 693.62,379 R24.2@697,375.62 697,391 711.81,405.81 711.81,430.94 Q4.4@739.87,459
NetR3_1: R3.1 U1.3 | length 56.9
  Bottom Layer w10: U1.3@152.62,585.8 152.62,597.62 178.38,623.38 R3.1@178.38,632
NetR4_1: R4.1 U1.8 | length 60.9
  Bottom Layer w25: U1.8@88.63,436.2 88.63,395.12 102.38,381.37 R4.1@102.38,381
NetR5_1: R5.1 U1.5 | length 180.3
  L4-BAT w15: v1(141,272.62) 177,308.62 v1(177,411)
  Bottom Layer w10: v1@181,410.53 184.12,413.64 U1.5@184.12,436.2
NetR15_1: R15.1 U3.3 | length 67.6
  Bottom Layer w20: U3.3@647.75,579.8 647.75,608.11 650.37,610.73 650.37,610.99 R15.1@675.38,636
NetR17_1: R17.1 U3.5 | length 259.1
  L4-BAT w15: v1(673.13,405) 673.13,294.18 710.66,256.65 743.59,256.65 v1(768,232.24)
  Bottom Layer w10: v1(673.13,405) 679.24,411.12 U3.5@679.24,430.2
NetR18_1: R18.1 U3.8 | length 54.3
  Bottom Layer w20: U3.8@584.76,430.2 584.76,393.24 584.45,392.93 R18.1@596.38,381
NetR20_1: R20.1 U1.6 | length 192.5
  L4-BAT w15: v1(94,268) 151.62,325.62 v1(151.62,415.38)
  Bottom Layer w10: v1(151.62,415.38) 152.62,416.38 U1.6@152.62,436.2
NetR23_1: R23.1 U3.6 | length 238.8
  L4-BAT w15: v1(647.75,409.38) 647.75,284.11 699.61,232.24 v1(719,232.24)
  Bottom Layer w10: v1(647.75,409.38) U3.6@647.75,430.2
VREF_OA: J2.4 R13.1 R16.1 | length 247.7
  Top Layer w20: R16.1@338.62,151 396,93.62 396,92.5 ; J2.4@396,47 396,92.5 ; R13.1@500.38,130 484.38,114 417.5,114 396,92.5

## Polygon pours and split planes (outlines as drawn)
IL2+ on Top Layer "Top Layer-No Net" (solid, remove dead copper, pour order 45): 510,509.83 583,509.83 613,509.83 617,505.83 618,504.83 618,486.83 618,454.83 626,446.83 655,417.83 655,274 643.83,262.83 563,262.83 521.13,262.83 508.13,275.83 507,276.96 507,317.83 507,507.83 509,509.83
BUS+ on Top Layer "Top Layer-No Net" (solid, remove dead copper, pour order 48): 546,804 545,803 545,779 545,778 540,773 527,773 527,772 500,745 500,658 500,540 506,534 624.27,534 624.27,789.73 603,811 602,811 596,817 594,819 554,819 549,819 545,815
IL1+ on Top Layer "Top Layer-No Net" (solid, remove dead copper, pour order 46): 16,510 89,510 119,510 123,506 124,505 124,487 124,455 132,447 137,442 137,366 137,289 134,286 17,286 13,290 13,318 13,508 15,510
BUS+ on Top Layer "Top Layer-No Net" (solid, remove dead copper, pour order 38): 24,987 53,987 316,987 318,985 318,868 317,867 295,867 190,867 131,808 131,755 131,542.96 121.76,533.72 117,528.96 92.19,528.96 19.04,528.96 10,538 10,974 12,976
GND on Top Layer "Top Layer-No Net" (solid, remove dead copper, pour order 44): 634,808 634,644 634,600 634,555 620,541 620,465 666,419 668,417 668,373 668,265 680,253 793,253 802,262 802,280 773,309 773,513 797,537 797,825 793,829 764,829 655,829
GND on Top Layer "Top Layer-No Net" (solid, remove dead copper, pour order 40): 143,805 143,617 121,595 121,481 131,471 168,434 168,408 168,258 183,243 224,243 242.68,243 283,283.32 283,539 283,559 283,847 277,853 191,853
BAT+ on Top Layer "Top Layer-No Net" (solid, remove dead copper, pour order 59): 815,869 976,869 990,855 990,598 990,494 982,486 814.39,486 805,495.39 805,859
NetC19_2 on Top Layer "Top Layer-No Net" (solid, remove dead copper, pour order 39): 785,469 785,314 816,283 840,283 980,283 990,293 990,470 987,473 789,473
NetC1_2 on Top Layer "Top Layer-No Net" (solid, remove dead copper, pour order 36): 294.24,471.05 294.24,259.72 318.11,235.85 478.11,235.85 490.11,247.85 492.11,249.85 492.11,287.85 492.11,471.98 487.09,477 300.18,477
BAT+ on Top Layer "Top Layer-No Net" (solid, remove dead copper, pour order 43): 295,495.09 299.09,491 481.96,491 495,504.04 495,753.03 527,785 591,785 618,812 654,848 795,848 937,848 980,848 985,853 990,858 990,865 990,955.13 955.13,990 525,990 525,860 523,858 344,858 295,809
GND on Bottom Layer "Top Layer-No Net" (solid, remove dead copper, pour order 52): 685.54,346 718,346 721,349 721,384 721,417 732,428 761,428 767.54,428 771,424.54 771,334 846,259 846,223 837,214 791,214 787.72,217.28 787.72,243.82 787.72,258 786.56,259 690,259 681,268 681,319 681,341.46
GND on Bottom Layer "Top Layer-No Net" (solid, remove dead copper, pour order 50): 610,832 610,680 621,669 772,669 784,681 784,832 775,841 619,841
GND on Bottom Layer "Top Layer-No Net" (solid, remove dead copper, pour order 37): 143,784 143,674 157,660 199,660 234,660 271,660 278,667 279,668 279,683 279,784 284,789 287,792 295,792 295,853 212,853
BAT+ on Bottom Layer "Top Layer-No Net" (solid, remove dead copper, pour order 47): 266,593 292,567 293,568 467,568 469,568 470,569 490,589 490,835 471,854 385,854 311,854 305,848 305,777 297,769 266,738
NetC1_2 on Bottom Layer "Top Layer-No Net" (solid, remove dead copper, pour order 60): 291,476 291,297 294,294 299,289 484,289 491,296 494,299 494,316 494,540 487,547 340,547 330,537 330,495 330,486 322,478 293,478
NetC19_2 on Bottom Layer "Top Layer-No Net" (solid, remove dead copper, pour order 61): 836,539 836,515 830,509 792,509 787,509 782,504 782,320 807.27,294.73 991.73,294.73 991.73,388 991.73,525.27 971,546 843,546
GND on Bottom Layer "Top Layer-No Net" (solid, remove dead copper, pour order 62): 175,290 175,253 191,237 269,237 286,254 286,425 282,429 280,431 260,431 237,431 231,425 230,424 230,415 230,387 175,332
BAT+ on Bottom Layer "Top Layer-No Net" (solid, remove dead copper, pour order 49): 793,851 793,560 985,560 990,565 990,980 980,990 861,990 628,990 618,980 618,872 631,859 785,859
BUS+ on Bottom Layer "Top Layer-No Net" (solid, remove dead copper, pour order 51): 10,571 123,571 131,579 131,789 207,865 477,865 500,842 500,597.22 507.22,590 559,590 598,629 598,966 574,990 31,990 22,990 10,978
BUS+ on L5-GND 1-PLANE "Top Layer-No Net" (solid, remove dead copper, pour order 42): 30,858 93,858 111,840 113,838 113,729 113,656 83,626 83,550 73,540 70,537 35,537 21.01,537 14.33,543.68 10,548.01 10,563 10,838 14.33,842.33
GND on L5-GND 1-PLANE "Top Layer-No Net" (solid, remove dead copper, pour order 54): 126,958 126,674 137,663 226,663 235,654 303,586 323,586 550,586 600,636 611,647 633,647 974,647 989,662 990,663 990,947 990,956 956,990 955,991 367,991 159,991
GND on L5-GND 1-PLANE "Top Layer-No Net" (solid, remove dead copper, pour order 66): 12,509 10,507 10,440 10,42 20,32 42,10 142,10 976,10 984,18 992,26 992,235 992,240 978,254 974,258 922,258 783,258 772,269 772,329 772,480 771.96,522 771.96,523.04 760,535 746,549 617,549 545,549 531,535 516,520 516,452 516,276 512,272 365,272 294,272 282,284 279,287 279,338 279,512 256,535 239,552 126,552 112,552 104,544 77,517 61,517 20,517
GND on L4-BAT "Top Layer-No Net" (solid, remove dead copper, pour order 85): 216,858 294,858 303,849 303,821 303,766 288,751 281,744 281,719 281,253 269,241 266,238 236,238 122,238 115,245 106,254 106,333 106,359 90,375 85,380 85,510 85,533 90,538 91,539 91,567 91,620 107,636 124,653 124,673 124,781 142,799 201,858 215,858
BUS+ on L4-BAT "Top Layer-No Net" (solid, remove dead copper, pour order 83): 203,871 309.14,871 318,879.86 318,978 311,985 240,985 19,985 14.33,980.33 14.33,856.54 14.33,553.67 25,543 28,540 45,540 77,540 87,550 87,591 87,629 113,655 118,660 118,706 118,781 164,827 178,841 208,871 209,871
BAT+ on L4-BAT "Top Layer-No Net" (solid, remove dead copper, pour order 81): 290,657 290,623 290,564 295,559 311,559 964,559 985.02,580.02 985.67,580.67 985.67,589.69 985.67,974.33 978,982 974,986 947,986 875,986 826,986 337,986 330.03,979.03 330.24,978.83 330.24,958 330.24,854.93 326.65,851.35 318,842.7 318,831 318,764 298,744 290,736 290,660
NetC1_2 on L4-BAT "Top Layer-No Net" (solid, remove dead copper, pour order 57): 290,460 290,314 290,300 305,285 430,285 466,285 477,296 477,377 477,481 469,489 357,489 299,489 290,480
NetC19_2 on L4-BAT "Top Layer-No Net" (solid, remove dead copper, pour order 58): 783.13,463 783.13,317 783.13,309.87 805,288 923.13,288 959.13,288 970.13,299 970.13,380 970.13,484 962.13,492 850.13,492 792.13,492 783.13,483
GND on L3-BUS "Top Layer-No Net" (solid, remove dead copper, pour order 79): 618,843 719.4,843 764,843 777,830 782,825 782,790 782,499 782,495 772,485 772,433 772,311 800,283 802,281 802,263 798,259 794,255 770,255 670,255 657,268 657,369 634,392 618,408 618,477 617,477 608,486 590,504 590,525 607,542 612,547 612,717 612,788 612,837
IL1+ on L3-BUS "Top Layer-No Net" (solid, remove dead copper, pour order 77): 14.33,509.14 14.33,354.37 14.33,294.67 23,286 48,286 121,286 126,291 128,293 128,324 128,437 128,453 116,465 64,517 38,517 22.19,517 14.33,509.14
IL2+ on L3-BUS "Top Layer-No Net" (solid, remove dead copper, pour order 75): 514,506 514,349 514,275 524,265 591,265 641.67,265 648,271.33 648,364 639,373 610,402 610,413 610,473 586,497 574,509 569,514 560,514 522,514 521.04,513.04
BAT+ on L3-BUS "Top Layer-No Net" (solid, remove dead copper, pour order 73): 558,976 558,904 558,865 558,861 559,860 564,855 590,855 781,855 792,844 796,840 796,796 796,557 803,550 806,547 820,547 972.39,547 985.67,560.28 985.67,617.54 985.67,968.33 973,981 970,984 874,984 566,984 558,976
NetC19_2 on L3-BUS "Top Layer-No Net" (solid, remove dead copper, pour order 55): 783.13,463 783.13,317 783.13,303 798.13,288 923.13,288 959.13,288 970.13,299 970.13,380 970.13,484 962.13,492 850.13,492 792.13,492 783.13,483
NetC1_2 on L3-BUS "Top Layer-No Net" (solid, remove dead copper, pour order 56): 290,460 290,314 290,300 305,285 430,285 466,285 477,296 477,377 477,481 469,489 357,489 299,489 290,480
BUS+ on L3-BUS "Top Layer-No Net" (solid, remove dead copper, pour order 69): 602,679 602,716 602,778 581,799 541,839 541,900 541,965 520,986 480,986 32,986 19,973 14.33,968.33 14.33,874.37 14.33,548.67 23,540 26,537 83,537 587,537 602,552
BUS+ on L2-GND-PLANE "Top Layer-No Net" (solid, remove dead copper, pour order 41): 14.33,842.33 14,842 14,733 14,542.46 14.33,542.13 16.46,540 24,540 70,540 86,540 88,542 88,614.35 88,641.63 112,665.63 115,668.63 115,690 115,836 93,858 30,858
GND on L2-GND-PLANE "Top Layer-No Net" (solid, remove dead copper, pour order 53): 162,565 949,565 990,606 990,965 990,971 969,992 967,990 161,990 136,965 136,591
GND on L2-GND-PLANE "Top Layer-No Net" (solid, remove dead copper, pour order 65): 12,509 10,507 10,440 10,42 20,32 42,10 142,10 976,10 984,18 992,26 992,235 992,240 978,254 974,258 922,258 797,258 779,276 772,283 772,329 772,480 771.96,480.04 771.96,522 771.96,523.04 760,535 746,549 617,549 545,549 531,535 516,520 516,452 516,276 512,272 365,272 294,272 282,284 279,287 279,338 279,512 256,535 239,552 126,552 112,552 104,544 77,517 61,517 20,517 12,509

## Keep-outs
Keep-Out Layer:
  circle w6: c62.87,929.25 r55.12
  circle w6: c936.87,62.99 r62.99
  circle w6: c62.99,62.99 r62.99
  circle w6: c937.01,937.01 r55.12
  lines w6: 10,10 990,10 990,990 10,990 10,10
  text ".Layer_Name" at 584.87,-858.49 h60

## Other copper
Top Layer:
  pour cut-out: 130.13,604.13 126,600 126,513.42 125.86,513.28 130.13,513.28
  pour cut-out: 122.2,565.07 122.2,552.39 123.01,553.19 123.01,563.32 121.02,565.31
  pour cut-out: 590.3,822.86 590.31,822.87 628.87,822.87 623.87,817.87 595.29,817.87
  text ".Layer_Name" at 584.87,-858.49 h60
L2-GND-PLANE:
  pour cut-out: 287,472 287,295 301,281 302,282 479.43,282 495,297.57 495,477 486,486 301,486
  pour cut-out: 780.13,475 780.13,298 794.13,284 795.13,285 972.56,285 988.13,300.57 988.13,480 979.13,489 794.13,489
  text ".Layer_Name" at 619.87,-866 h60
L5-GND 1-PLANE:
  pour cut-out: 287,472 287,295 301,281 302,282 479.43,282 495,297.57 495,477 486,486 301,486
  pour cut-out: 780.13,475 780.13,298 794.13,284 795.13,285 972.56,285 988.13,300.57 988.13,480 979.13,489 794.13,489
  text ".Layer_Name" at 647.87,-860 h60
L3-BUS:
  text ".LAYER_Name" at 566,-853 h60
L4-BAT:
  text ".LAYER_Name" at 609,-853 h60
Bottom Layer:
  text ".Layer_Name" at 584.87,-858.49 h60

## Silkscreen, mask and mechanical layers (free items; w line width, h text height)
Top Overlay:
  lines w6: 18,611 10,619 10,777 18,785
  text ".Layer_Name" at 584.87,-858.49 h60
Bottom Overlay:
  lines w6: 206,654 212,660 212,663 212,690 216,694 ; 535,768 554,768 560,762 ; 536,661 571,661 576,656 ; 654,252 654,261 666,273 ; 686,666 693,666 697,670
  text "TIDA-00705" at 708,940 h40
  text "Rev E1" at 567,888 h40
  text ".Layer_Name" at 584.87,-858.49 h60
Top Paste:
  text ".Layer_Name" at 584.87,-858.49 h60
Bottom Paste:
  text ".Layer_Name" at 584.87,-858.49 h60
Top Solder:
  text ".Layer_Name" at 584.87,-858.49 h60
  text ".Layer_Name" at 584.87,-858.49 h60
Bottom Solder:
  text ".Layer_Name" at 584.87,-858.49 h60
Drill Guide:
  text ".Layer_Name" at 584.87,-858.49 h60
M1 Board Outline:
  the board outline again, w6
M2 Board Dimensions:
  rectangle: 7.37,-285.5 132.37,-160.5
  rectangle: 132.37,-410.5 507.37,-285.5
  lines w7: 7.37,-285.5 1007.37,-285.5 ; 132.37,-410.5 132.37,-160.5 ; 257.37,-410.5 257.37,-160.5 ; 507.37,-410.5 507.37,-160.5 ; 757.37,-410.5 757.37,-160.5 ; 7.37,-410.5 1007.37,-410.5 1007.37,-160.5 7.37,-160.5 7.37,-410.5
  lines w10: 7.37,-475.5 7.37,-455.5 ; 67.37,-485.5 7.37,-465.5 ; 67.37,-445.5 7.37,-465.5 ; 231.46,-465.5 7.37,-465.5 ; 783.29,-465.5 1007.37,-465.5 ; 947.37,-485.5 1007.37,-465.5 ; 947.37,-445.5 1007.37,-465.5 ; 1007.37,-475.5 1007.37,-455.5
  text "1000 (mil)" at 241.46,-501.49 h60
M3 3D STEP Top:
  text ".Layer_Name" at 584.87,-858.49 h60
M4 3D STEP Bottom:
  text ".Layer_Name" at 584.87,-858.49 h60
M5 Assembly Top:
  circle w10: c165,48 r6.32
  circle w10: c547,46 r6
  circle w10: c730,59 r3.61
  lines w10: -284.13,-930.17 6315.87,-930.17 ; -284.13,-726.83 6317.87,-726.83 ; -284.13,-523.5 -284.13,-1133.5 3720.87,-1133.5 6317.87,-1133.5 6317.87,-523.5 -283.63,-523.5 -283.63,-1133.5 1291.87,-1133.5 ; 2180.87,-1133.5 2180.87,-523.5 ; 3742.87,-726 3742.87,-522.67 ; 4287.87,-726.83 4287.87,-523.5 ; 4909.87,-1140 4909.87,-937.17
  text "COMPONENTS MARKED 'DNP' SHOULD NOT BE POPULATED." at 1161.37,-318.5 h30
  text "ASSEMBLY VARIANT:" at 1160.87,-434 h30
  text ".VariantName" at 2196.87,-434 h30
  text ".LAYER_Name" at 567,-849 h60
M6 Assembly Bottom:
  lines w10: -284.5,-734.33 6317.5,-734.33 ; -282.5,-937.67 6317.5,-937.67 ; 1123.5,-1147.5 1123.5,-944.67 ; 1745.5,-734.33 1745.5,-531 ; 2244,-730 2244,-526.67 ; 3852.5,-1141 3852.5,-531 ; 4741.5,-1141 6317,-1141 6317,-531 -284.5,-531 -284.5,-1141 2312.5,-1141 6317.5,-1141 6317.5,-531
  text "COMPONENTS MARKED 'DNP' SHOULD NOT BE POPULATED." at 6110,-325 h60
  text ".VariantName" at 5066,-441 h60
  text "ASSEMBLY VARIANT:" at 6105,-441 h60
  text "REV: E1" at 2181,-662 h60
  text ".VersionControl_RevNumber" at 1043.5,-663.17 h60
  text "SVN REV:" at 1549.5,-663.17 h60
  text "BOARD #:" at 3777.5,-663.17 h60
  text "PCB VIEWED FROM BOTTOM SIDE" at 6254,-663.17 h60
  text ".prj_number" at 3228.02,-663.89 h60
  text ".layer_Name" at 5105.02,-859.89 h35
  text "IGNORE ->" at 2555.85,-865.49 h60
  text "TEXAS INSTRUMENTS" at 912.5,-1071.84 h60
  text ".Print_Time" at 2177,-1071.84 h60
  text ".Print_Date" at 2906,-1071.84 h60
  text "GENERATED    :" at 3775.5,-1071.84 h60
  text ".plot_File_Name" at 5448.5,-1071.84 h60
  text "PLOT NAME =" at 6254,-1071.84 h60
M9 Title Sheet:
  drawing of 56 lines, arcs and shapes, not listed
  text "1" at 320.58,8044.9 h70
  text "2" at 3262.11,8044.9 h70
  text "3" at 5702.71,8044.9 h70
  text "4" at 8212.65,8044.9 h70
  text "5" at 10776.84,8044.9 h70
  text "6" at 13282.14,8044.9 h70
  text "A" at -399.13,6895.37 h70
  text "A" at 14398.02,6895.37 h70
  text "B" at -399.13,4636.49 h70
  text "B" at 14398.02,4636.49 h70
  text "C" at -399.13,2204.83 h70
  text "C" at 14398.02,2204.83 h70
  text "PROJECT TITLE:" at 11348.77,257.82 h45
  text ".PRJ_Title" at 11440.27,127.32 h70
  text "DESIGNED FOR:" at 11335.61,-31.74 h45
  text ".PRJ_Customer" at 11385.61,-171.74 h70
  text "D" at -399.13,-301.67 h70
  text "D" at 14398.02,-301.67 h70
  text "FILE NAME:" at 11347.5,-340.46 h45
  text ".PCB_File_Name_No_Path" at 11397.5,-460.46 h70
  text "ENGINEER:" at 11346.95,-611.59 h45
  text "LAYOUT BY:" at 12838.93,-618.58 h45
  text "Texas Instruments (TI) and/or its licensors do not warrant the accuracy or completeness of this specification" at 6354,-620.34 h45
  text "or any information contained therein. TI and/or its licensors do not warrant that this design will meet" at 6309.01,-733 h45
  text ".PRJ_Engineer" at 11396.95,-766.58 h70
  text ".pcb_Layout" at 12889.43,-773.57 h70
  text "the specifications, will be suitable for your application or fit for any particular purpose, or will operate in" at 6309.01,-845.67 h45
  text "ALTIUM DESIGNER VERSION:" at 12898.63,-941.77 h45
  text "an implementation. TI and/or its licensors do not warrant that the design is production worthy. You should" at 6309.01,-958.33 h45
  text ".print_Scale" at 11409.34,-1034.04 h70
  text "completely validate and test your design implementation to confirm the system functionality for your application." at 6354,-1071 h45
  text ".Application_BuildNumber" at 12949.13,-1075.1 h70
  text "2" at 3053.82,-1263.03 h70
  text "6" at 13023.96,-1272.7 h70
  text "3" at 5383.82,-1277.08 h70
  text "5" at 10535.37,-1280.62 h70
  text "4" at 7991.08,-1283.6 h70
  text "1" at 443.36,-1291.02 h70
M10 Fab Notes:
  drawing of 220 lines, arcs and shapes, not listed
  text "DESIGN INFORMATION" at 12388.89,6810 h60
  text "(REFER ALSO ARRAY/PANEL PROFILING INFORMATION)" at 12027.33,6648.29 h60
  text "BOARD SIZE" at 11341.33,6644 h60
  text "1000MIL" at 11803.65,6516.18 h60
  text "X" at 12309.33,6516.18 h60
  text "1000MIL" at 12540.65,6516.18 h60
  text "Number of Layers :" at 11744.33,6319 h60
  text "6" at 12839.14,6309 h60
  text "MIN. TRACK WIDTH:" at 11744.33,6180 h60
  text "8" at 12840.58,6180 h60
  text "MIL" at 12995.33,6180 h60
  text "MIN. CLEARANCE:" at 11744.33,6048 h60
  text "MIL" at 12995.33,6048 h60
  text "7.6" at 12787,6047 h60
  text "MIN. VIA PAD SIZE:" at 11744.33,5916 h60
  text "16" at 12810.59,5916 h60
  text "MIL" at 12995.33,5916 h60
  text "0.127mm (5MIL)" at 12439.33,5774.29 h60
  text "EXTERNAL" at 13189.87,5772 h60
  text "MINIMUM ANNULAR RING" at 11415.1,5770 h60
  text "PER" at 11615.1,5652 h60
  text "IPC-D-275 CLASS 2 LEVEL C" at 11835.1,5652 h60
  text "MIL, HOLES" at 13323.33,5539.71 h60
  text "+/-" at 12930.87,5539 h60
  text "+/-" at 13784.87,5539 h60
  text "REGISTRATION TOLERANCES:" at 11415.1,5534 h60
  text "METAL" at 12614.87,5534 h60
  text "5" at 13191.08,5534 h60
  text "3" at 14024.08,5534 h60
  text "MIL" at 14140.33,5534 h60
  text "MATERIAL:" at 11340.33,5324.54 h60
  text "FR-4 High Tg" at 12326.78,5184.21 h60
  text "FR-408" at 11761.33,5175.64 h60
  text "OTHER" at 13249.33,5175.64 h60
  text "X" at 12173,5174 h60
  text "63 MIL (1.6mm) +/-10%" at 12081.44,5012.92 h60
  text "THICKNESS:" at 11415.1,5008.64 h60
  text "X" at 11953.27,5008.64 h60
  text "OTHER" at 13366.33,5008.64 h60
  text "TOLERANCE:" at 11415.1,4850.64 h60
  text "X" at 12254.41,4850.64 h60
  text "ANSI IPC-6012 TYPE 3 CLASS 2" at 12441.35,4850.64 h60
  text "OTHER +/-" at 12441.33,4694.64 h60
  text "BOW & TWIST:" at 11415.1,4537.64 h60
  text "X" at 12254.41,4537.64 h60
  text "ANSI IPC-6012 TYPE 3 CLASS 2" at 12441.35,4537.64 h60
  text "OTHER +/-" at 12441.33,4379.13 h60
  text "COPPER THICKNESS (FINISHED):" at 11340.33,4243.64 h60
  text "X" at 13588,4094 h60
  text "1.4MIL (1oz)" at 12220.33,4090.92 h60
  text "2MIL (1.4oz)" at 12987.33,4090.92 h60
  text "2.8MIL (2oz)" at 13714.33,4090.92 h60
  text "OUTER:" at 11697.33,4086.64 h60
  text "1.4MIL (1oz)" at 12220.33,3933.92 h60
  text "2.8MIL (2oz)" at 12987.33,3933.92 h60
  text "N/A" at 13713.87,3934.29 h60
  text "INNER SIGNAL:" at 11408.25,3929.64 h60
  text "X" at 12852,3923 h60
  text "DRILLING:" at 11340.33,3790.64 h60
  text "REFERENCE:" at 11415.1,3673.64 h60
  text "X" at 12063.33,3673.64 h60
  text "AS SHOWN" at 12250.33,3673.64 h60
  text "X" at 12964.33,3673.64 h60
  text "NC_DRILL FILES" at 13101.33,3673.64 h60
  text "PTH MIN COPPER THICKNESS:" at 11415.1,3515.64 h60
  text "X" at 12765.33,3515.64 h60
  text "1MIL" at 12902.33,3515.64 h60
  text "OTHER" at 13399.33,3515.64 h60
  text "BOARD FINISH:" at 11340.33,3356.64 h60
  text "SILKSCREEN:" at 11495.56,3238.64 h60
  text "X" at 12444.33,3238.64 h60
  text "TOP" at 12570.33,3238.64 h60
  text "X" at 12954.33,3238.64 h60
  text "BOTTOM" at 13081.33,3238.64 h60
  text "SILKSCREEN COLOR:" at 11493.89,3072.64 h60
  text "X" at 12441.62,3072.64 h60
  text "WHITE" at 12568.66,3072.64 h60
  text "OTHER" at 13079.66,3072.64 h60
  text "SOLDER RESIST COLOR:" at 11599.89,2921.64 h60
  text "GREEN" at 12294.66,2762.44 h60
  text "X" at 12056.87,2750 h60
  text "BLUE" at 12864.87,2744 h60
  text "OTHER" at 13313.87,2740 h60
  text "IMMERSION GOLD (ENIG)" at 12401.33,2553.92 h60
  text "ENEPIG" at 13738.87,2550.64 h60
  text "SURFACE FINISH:" at 11340.33,2549.64 h60
  text "X" at 12214.39,2549.64 h60
  text "IMM. TIN/SILVER OR EQUIV" at 11669.87,2392.64 h60
  text "OTHER" at 13101.33,2392.64 h60
  text "ARRAY/PANEL:" at 11340.33,2213.64 h60
  text "CUT AND TRIM PER MECH LAYER 1" at 12401.33,2209.35 h60
  text "N.C. ROUTE" at 12401.33,2057.64 h60
  text "X" at 13080.33,2057.64 h60
  text "V. SCORE" at 13267.33,2057.64 h60
  text "CERTIFICATION:" at 11340.33,1920.64 h60
  text "MATERIALS AND WORKMANSHIP FOR ALL PCBS" at 12065.33,1920.64 h60
  text "TO MEET OR EXCEED THE REQUIREMENTS OF:" at 12065.33,1822.64 h60
  text "X" at 11691.84,1686.13 h60
  text "ANSI IPC-A-600F CLASS ->" at 11830.84,1686.13 h60
  text "X" at 13469.89,1686.13 h60
  text "2" at 13588.84,1686.14 h60
  text "1" at 13273.84,1684.64 h60
  text "3" at 13942.84,1684.64 h60
  text "X" at 11693.89,1526.64 h60
  text "UL 94V-0" at 11830.84,1526.64 h60
  text "X" at 12505.89,1526.64 h60
  text "RoHS" at 12642.84,1526.64 h60
  text "OTHER" at 13287.24,1526.64 h60
  text "PER ORDER" at 13684.3,1526.64 h60
  text "ADDITIONAL REQUIREMENTS:" at 11340.33,1385.64 h60
  text "X" at 13948,1298 h60
  text "VIA TENTING:" at 12814.87,1292.36 h60
  text "YES" at 13386.54,1283.28 h60
  text "NO" at 13781.35,1283.05 h60
  text "MICROSECTION:" at 11415.1,1270.64 h60
  text "YES" at 12320.84,1270.64 h60
  text "REQUIRED" at 13182.33,1114.49 h60
  text "BARE BOARD ELEC. TEST:" at 11415.1,1111.64 h60
  text "NONE" at 12720.84,1111.64 h60
  text "X" at 13055.33,1111.64 h60
  text "PER ORDER" at 13774.33,1111.64 h60
  text "MANUFACTURER'S UL:" at 11415.1,954.64 h60
  text "RAIL" at 12580.84,950.35 h60
  text "METAL" at 13072.65,950.35 h60
  text "X" at 13447.87,950 h60
  text "SILK" at 13584.33,950.35 h60
M11 Gerber Information:
  lines w10: -284.13,-930.17 6315.87,-930.17 ; -284.13,-726.83 6317.87,-726.83 ; -284.13,-523.5 -284.13,-1133.5 3720.87,-1133.5 6317.87,-1133.5 6317.87,-523.5 -283.63,-523.5 -283.63,-1133.5 1291.87,-1133.5 ; 2180.87,-1133.5 2180.87,-523.5 ; 3697.87,-730 3697.87,-526.67 ; 4287.87,-726.83 4287.87,-523.5 ; 4909.87,-1140 4909.87,-937.17
  text "ALL ARTWORK VIEWED FROM TOP SIDE" at -220.63,-655.67 h60
  text "BOARD #:" at 2255.87,-655.67 h60
  text "SVN REV:" at 4483.87,-655.67 h60
  text ".VersionControl_RevNumber" at 4989.87,-655.67 h60
  text "REV: E1" at 3792.87,-657 h60
  text "BI-DIR-LES" at 2783,-661 h60
  text "LAYER NAME =" at -220.63,-858.49 h60
  text "PLOT NAME =" at -220.63,-1064.34 h60
  text ".plot_File_Name" at 584.87,-1064.34 h60
  text "GENERATED    :" at 2257.87,-1064.34 h60
  text ".Print_Date" at 3127.37,-1064.34 h60
  text ".Print_Time" at 3856.37,-1064.34 h60
  text "TEXAS INSTRUMENTS" at 5120.87,-1064.34 h60
M12 Stackup:
  drawing of 399 lines, arcs and shapes, not listed
  text "Layer" at 6315,7505 h60
  text "Name" at 6724.91,7505 h60
  text "Material" at 7674.65,7505 h60
  text "Thickness" at 8534.42,7505 h60
  text "Constant" at 9184.25,7505 h60
  text "Board Layer Stack" at 9754.11,7505 h60
  text "1" at 6315,7385 h60
  text "Top Overlay" at 6724.91,7385 h60
  text "2" at 6315,7265 h60
  text "Top Solder" at 6724.91,7265 h60
  text "Solder Resist" at 7674.65,7265 h60
  text "0" at 9184.25,7265 h60
  text "3" at 6315,7145 h60
  text "Top Layer" at 6724.91,7145 h60
  text "Copper" at 7674.65,7145 h60
  text "4" at 6315,7025 h60
  text "Dielectric1" at 6724.91,7025 h60
  text "FR-4 High Tg" at 7674.65,7025 h60
  text "0" at 9184.25,7025 h60
  text "5" at 6315,6905 h60
  text "L2-GND-PLANE" at 6724.91,6905 h60
  text "Copper" at 7674.65,6905 h60
  text "6" at 6315,6785 h60
  text "Dielectric2" at 6724.91,6785 h60
  text "FR-4 High Tg" at 7674.65,6785 h60
  text "0" at 9184.25,6785 h60
  text "7" at 6315,6665 h60
  text "L3-BUS" at 6724.91,6665 h60
  text "Copper" at 7674.65,6665 h60
  text "8" at 6315,6545 h60
  text "Dielectric 3" at 6724.91,6545 h60
  text "FR-4 High Tg" at 7674.65,6545 h60
  text "0" at 9184.25,6545 h60
  text "9" at 6315,6425 h60
  text "L4-BAT" at 6724.91,6425 h60
  text "Copper" at 7674.65,6425 h60
  text "10" at 6315,6305 h60
  text "Dielectric 4" at 6724.91,6305 h60
  text "FR-4 High Tg" at 7674.65,6305 h60
  text "0" at 9184.25,6305 h60
  text "11" at 6315,6185 h60
  text "L5-GND 1-PLANE" at 6724.91,6185 h60
  text "Copper" at 7674.65,6185 h60
  text "12" at 6315,6065 h60
  text "Dielectric5" at 6724.91,6065 h60
  text "FR-4 High Tg" at 7674.65,6065 h60
  text "0" at 9184.25,6065 h60
  text "13" at 6315,5945 h60
  text "Bottom Layer" at 6724.91,5945 h60
  text "Copper" at 7674.65,5945 h60
  text "14" at 6315,5825 h60
  text "Bottom Solder" at 6724.91,5825 h60
  text "Solder Resist" at 7674.65,5825 h60
  text "0" at 9184.25,5825 h60
  text "15" at 6315,5705 h60
  text "Bottom Overlay" at 6724.91,5705 h60
M13 Component Bodies Top:
  text ".Layer_Name" at 584.87,-858.49 h60
M14 Component Bodies Bottom:
  text ".Layer_Name" at 584.87,-858.49 h60
M15 Courtyards Top:
  text ".Layer_Name" at 584.87,-858.49 h60
M16 Courtyards Bottom:
  text ".Layer_Name" at 584.87,-858.49 h60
